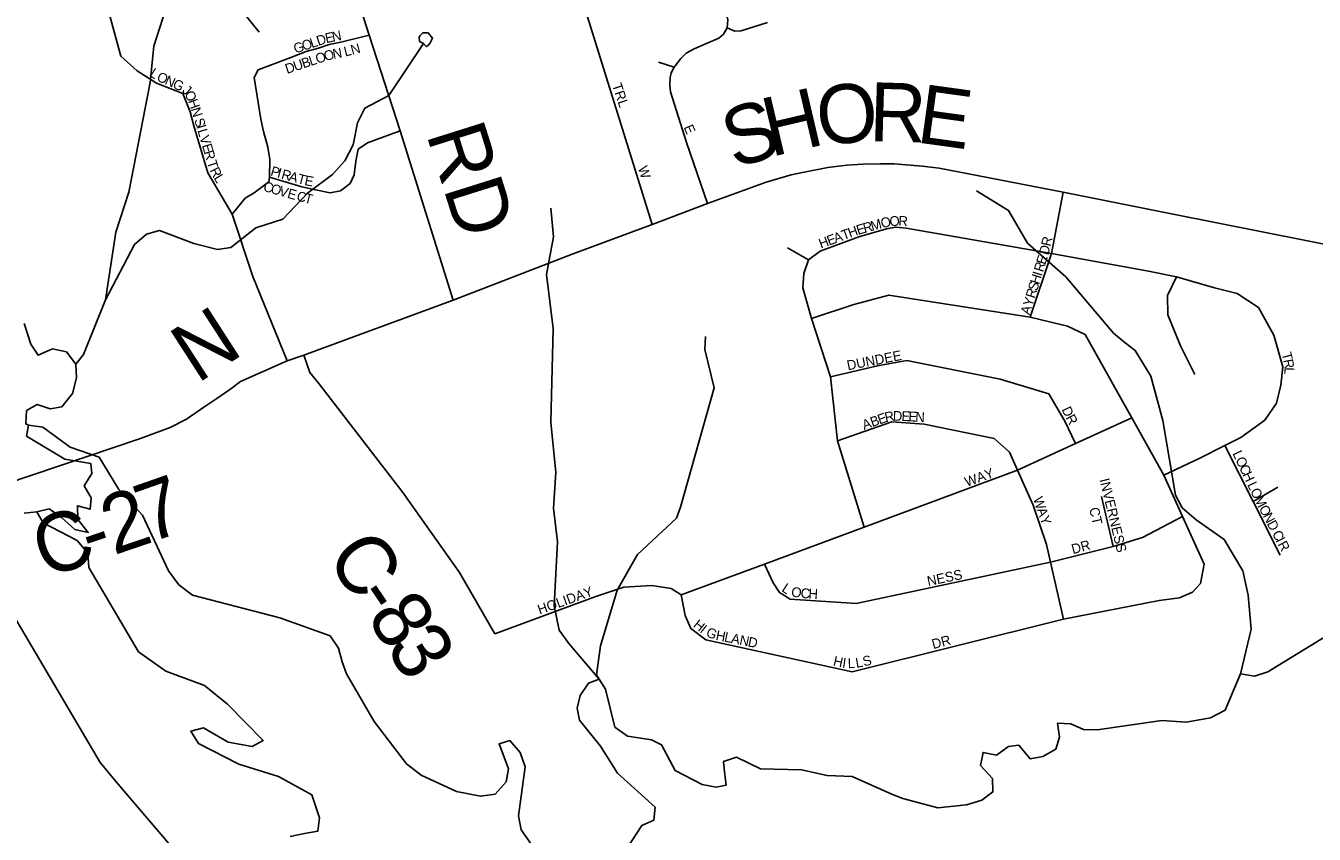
# Model space of a CAD drawing. Extents: x 1525783 to 1900577, y 218250 to 627376.
# Drawn here: x 1688647 to 1695217, y 435775 to 439896 of the extents above; entities that cross this region are included whole.
import ezdxf

# ---------------------------------------------------------------- set-up
doc = ezdxf.new("R2010")
doc.units = 0
for name, color, linetype in [('GM_X_County_Road', 7, 'Continuous'), ('GM_X_County_Road_Text', 7, 'Continuous'), ('GM_X_Major_Lake', 7, 'Continuous'), ('GM_X_Minor_Lake', 7, 'Continuous'), ('GM_X_Minor_River', 7, 'Continuous'), ('GM_X_Township_Subdivision', 7, 'Continuous'), ('GM_X_Township_Subdivision_Text', 7, 'Continuous')]:
    doc.layers.add(name, color=color, linetype=linetype)

msp = doc.modelspace()

# ---------------------------------------------------------------- linework, layer by layer
at = {"layer": 'GM_X_County_Road'}
for points in [[(1690827.2, 438497.9), (1690557, 439360.3), (1690398, 439848), (1690158, 440598.1), (1689926.7, 441314.4), (1689520.4, 442560), (1689115.8, 443745.4), (1689169.3, 444557.8), (1689169.8, 444609.9)], [(1690065.6, 438217.8), (1690827.2, 438497.9), (1691434.1, 438731.3), (1691842, 438883.6), (1692122.7, 438990.2), (1692422, 439099.7), (1692550.4, 439135.8), (1692617.2, 439150.5), (1692737.5, 439173.3), (1692833.7, 439185.3), (1692915.2, 439190.7), (1693002.1, 439192), (1693075.6, 439192), (1693217.3, 439181.3), (1693304.2, 439170.6), (1693499.3, 439133.2), (1693936.3, 439049), (1694498.6, 438936.3), (1695843.2, 438668.9)], [(1684258.4, 435873.5), (1685061.4, 436166), (1686588.5, 436826.7), (1686722.3, 436878.2), (1686872.7, 436936), (1687511.7, 437185.9), (1687952.9, 437335.6), (1688247.6, 437451.6), (1688404.4, 437513.3), (1689227.7, 437790.2), (1689382.5, 437849.2), (1689466, 437891), (1689559.4, 437954.9), (1689620.8, 437996.6), (1689692.1, 438045.8), (1689741.2, 438082.6), (1689979.6, 438188.3), (1690065.6, 438217.8)], [(1691038.4, 436797), (1690859.5, 437110.1), (1690569.3, 437517.5), (1690141.7, 438072.8), (1690095, 438129.3), (1690065.6, 438217.8)]]:
    msp.add_lwpolyline(points, dxfattribs=at)
at = {"layer": 'GM_X_Major_Lake'}
for points in [[(1691270.8, 435660.6), (1691173.1, 435796.8), (1691160.4, 435869.2), (1691193.2, 436119.2), (1691168.5, 436191.9), (1691115.5, 436253), (1691061, 436235.9), (1691108.8, 436108.7), (1691097.5, 436042.7), (1691040.2, 435979.6), (1690965.8, 435968.9), (1690843.9, 435993.1), (1690663, 436076.5), (1690587.9, 436134), (1690423.5, 436349.5), (1690281.7, 436592.7), (1690260.8, 436653.2), (1690242, 436723.7), (1690199.1, 436786.6), (1689942.1, 436877.5), (1689497.2, 436993.7), (1689428, 437047), (1689375.2, 437118.2), (1689242.1, 437401.3), (1689122.3, 437531.8), (1689021.1, 437698), (1688873.7, 437748.8), (1688733.2, 437849.5), (1688661.3, 437860.9), (1688650.2, 437804.9), (1688846.5, 437687.1), (1688978.4, 437664.7), (1688983.5, 437614.5), (1688944.2, 437551), (1688981.1, 437490.2), (1688976, 437432.1), (1688910.2, 437449.3), (1688912.9, 437379.1), (1688965.8, 437314), (1688897.9, 437329.2), (1688828.9, 437390.6), (1688765.6, 437433.9), (1688703.1, 437418.9), (1688736.1, 437362.2), (1688908.9, 437272.9), (1688963.8, 437207.7), (1688968.5, 437135.5), (1689221.1, 436705.8), (1689361.6, 436607.1), (1689558.8, 436533.4), (1689675.3, 436439), (1689858.3, 436253.3), (1689801.6, 436222.2), (1689679.7, 436244.5), (1689552.7, 436316.9), (1689488.2, 436300), (1689527.2, 436237.2), (1689733.7, 436133.2), (1689935.1, 436069.5), (1690105.8, 435976.2), (1690145.7, 435859.2), (1690136.4, 435791.1), (1690068, 435778.3), (1689995.5, 435763.6)], [(1695471.2, 436903.9), (1694980.3, 436603.7), (1694913.6, 436580.8), (1694841.7, 436592.1), (1694764, 436407), (1694689, 436368.2), (1694564.3, 436346.3), (1694440.1, 436354.5), (1694110.4, 436308.2), (1694040.2, 436309.4), (1693976.6, 436338.6), (1693908.5, 436341.8), (1693919.1, 436269.4), (1693900, 436209.6), (1693833.1, 436170.7), (1693768.7, 436159.8), (1693711.8, 436229), (1693657.5, 436221.9), (1693596.6, 436178.9), (1693528.6, 436192.1), (1693515.4, 436126.2), (1693576.3, 436058.9), (1693579, 435990.7), (1693522.1, 435949.6), (1693443.4, 435924.9), (1693298.8, 435909.4), (1693119.2, 435956.7), (1693067.4, 435977.7), (1692860.6, 436069.6), (1692734.3, 436073.8), (1692602.6, 436104.2), (1692394.1, 436107.9), (1692270.9, 436168.3), (1692204.3, 436145.4), (1692209.3, 436093.2), (1692218.1, 436024.8), (1692167.8, 436015.7)], [(1692167.8, 436015.7), (1692095.8, 436029), (1691958.8, 436099.6), (1691889.1, 436231.2), (1691837.4, 436256.2), (1691715.4, 436274.4), (1691650.2, 436321.7), (1691603.6, 436515), (1691570.5, 436565.7), (1691516, 436544.6), (1691474.7, 436483.2), (1691459.4, 436417.3), (1691470.3, 436356.9), (1691578.1, 436224.7), (1691663.8, 436086.8), (1691857.1, 435912.9), (1691849.8, 435846.9), (1691789.1, 435819.9), (1691712.8, 435702.9)]]:
    msp.add_lwpolyline(points, dxfattribs=at)
at = {"layer": 'GM_X_Minor_Lake'}
for points in [[(1690674.6, 439806.2), (1690688.3, 439790), (1690700.5, 439797.8), (1690708.8, 439809.6), (1690721.2, 439833.5), (1690699.7, 439859.9), (1690671.6, 439860.5), (1690657.3, 439844.7), (1690653.1, 439836.7), (1690654.7, 439816.6)], [(1690654.7, 439816.6), (1690674.6, 439806.2)]]:
    msp.add_lwpolyline(points, dxfattribs=at)
at = {"layer": 'GM_X_Minor_River'}
for points in [[(1689054.1, 438499.6), (1689106.7, 438843.5), (1689172.7, 439048.9), (1689281.4, 439606.5), (1689300.9, 439792.7), (1689360.6, 439982.1)], [(1688901.6, 438171.4), (1688940.7, 438220.8), (1689054.1, 438499.6), (1689201.8, 438781.7), (1689262.9, 438834.7), (1689329.4, 438853.6), (1689504.6, 438786.3), (1689624.4, 438756.1), (1689692.7, 438766.9), (1689820.9, 438866.9), (1689958.1, 438910.6), (1690082.9, 439042.7), (1690211, 439138.7), (1690274.4, 439207.7), (1690316, 439289.2), (1690338.2, 439401.1), (1690375.7, 439476.7), (1690499.2, 439540.6), (1690674.6, 439806.2)], [(1694841.7, 436592.1), (1694896.1, 436819.8), (1694881.3, 436994.5), (1694853.5, 437117.3), (1694758.2, 437277.4), (1694615.7, 437378.2), (1694544.7, 437439.6), (1694509.8, 437504.4), (1694444.7, 437884.5), (1694384.7, 438110.2), (1694305, 438241.9), (1694253.6, 438280.9), (1694194.3, 438330.1), (1693951, 438617.1), (1693755.7, 438789), (1693658.5, 438955.2), (1693495.9, 439054.3)], [(1691570.5, 436565.7), (1691415.5, 436746.9), (1691366.6, 436816), (1691340.9, 436938.8), (1691359, 437265.3), (1691338.2, 437438.1), (1691349.6, 437618.4), (1691324.3, 437875.5), (1691337.2, 438352.6), (1691302.2, 438627.9), (1691337.9, 438819.8), (1691324.6, 438966.4)], [(1688661.3, 437860.9), (1688647.3, 437867.1), (1688650.6, 437935.2), (1688705.3, 437966.3), (1688771.1, 437943.1), (1688831.4, 437954.1), (1688884.8, 438021.3), (1688906.3, 438101.1), (1688901.6, 438171.4), (1688854.7, 438234.4), (1688782.8, 438249.7), (1688710, 438216.9), (1688673, 438273.8), (1688638.8, 438378.6)], [(1691570.5, 436565.7), (1691556.9, 436588), (1691577.7, 436736), (1691663.2, 437019.3), (1691766.9, 437201.9), (1691964.8, 437386.9), (1691985.9, 437442.7), (1692157.7, 438051.2), (1692109.2, 438246.6), (1692112.5, 438312.7)], [(1688703.1, 437418.9), (1688638.8, 437412.1)]]:
    msp.add_lwpolyline(points, dxfattribs=at)
at = {"layer": 'GM_X_Township_Subdivision'}
for points in [[(1692122.7, 438990.2), (1692015.7, 439300.6), (1691934.2, 439560.3), (1691930.7, 439595.2), (1691933.1, 439632.5), (1691938.9, 439655.8), (1691952.8, 439684.9), (1691987.8, 439730.4), (1692014.6, 439756), (1692055.3, 439778.1), (1692181.1, 439834), (1692205.6, 439853.8), (1692223.1, 439885.3), (1692226.6, 439927.2), (1692220.7, 439957.5), (1692074, 440371), (1692053, 440405.9), (1692029.7, 440418.7)], [(1689979.6, 438188.3), (1689805.1, 438618.3), (1689699.5, 438935.2), (1689576.1, 439147.1), (1689504.1, 439386.7), (1689484.7, 439457.1), (1689447.4, 439551.8), (1689313.5, 439603.2), (1689215.8, 439666.3), (1689132.3, 439741.4), (1689076, 439946.7), (1689298.3, 440127.4), (1689449.6, 440220.6), (1689569.2, 440197.9), (1689837, 439863.8)], [(1691842, 438883.6), (1691455.5, 440124), (1691449.7, 440161.3), (1691455.5, 440203.2)], [(1692295.5, 439870.9), (1692429, 439913.2)], [(1690398, 439848), (1690252.9, 439812.5), (1690194, 439801.2), (1690139, 439782.2), (1690076.3, 439765.1), (1689998.5, 439734.7), (1689880.7, 439691), (1689831.3, 439672), (1689811.4, 439632.1), (1689845.4, 439419.7), (1689858.9, 439357.4), (1689880.7, 439277.2), (1689892.2, 439214.5), (1689890, 439125.3), (1689886.6, 439100.1), (1689811.9, 439044.6), (1689765.5, 439016.9), (1689699.5, 438935.2)], [(1692223.1, 439885.3), (1692262.5, 439869.6), (1692295.5, 439870.9)], [(1691952.8, 439684.9), (1691873.7, 439710.6)], [(1690557, 439360.3), (1690390, 439300.3), (1690341.5, 439266.7), (1690330.9, 439206.5), (1690322.3, 439136.3), (1690301.8, 439092.4), (1690251.3, 439054.7), (1690199, 439045.1), (1690125, 439059.8), (1690055.5, 439075), (1689890, 439125.3)], [(1693873.8, 438725), (1693877.5, 438736.2), (1693936.3, 439049)], [(1692921.5, 437340.2), (1692786.8, 437780.9), (1692750.8, 438106.7), (1692654.6, 438403.4), (1692609.1, 438561.1), (1692614.5, 438633.3), (1692638.6, 438702.8), (1692697.4, 438748.2), (1692895.2, 438820.4), (1693036.8, 438860.5), (1693083.6, 438869.9), (1693137.1, 438864.5), (1693877.5, 438736.2), (1694372, 438645.3), (1694515, 438617.3), (1694708.8, 438560.4), (1694824.4, 438531.6), (1694932.9, 438460.9), (1695011.7, 438318.7), (1695058, 438157.1), (1695047.8, 438065.1), (1695025.5, 437973.3), (1694965.4, 437886.5), (1694843, 437797), (1694762.1, 437756.1), (1694634.1, 437691.5), (1694449.7, 437605.6)], [(1692531.6, 438763.8), (1692638.6, 438702.8)], [(1693769.5, 438411.8), (1693873.8, 438725)], [(1694608.2, 438119.4), (1694535.5, 438265.6), (1694471.2, 438423.5), (1694469.5, 438521.9), (1694515, 438617.3)], [(1691988.5, 436994.8), (1692010.3, 436890.4), (1692038.8, 436823.6), (1692115.5, 436765.6), (1692861, 436603.7), (1693939.4, 436871.3), (1694426.5, 436966.2), (1694531, 436979.8), (1694595.9, 437008.4), (1694637, 437053.6), (1694655.3, 437151.5), (1694545.1, 437394.9), (1694449.7, 437605.6), (1694287, 437897.5), (1694050, 438323), (1693958.8, 438365.3), (1693769.5, 438411.8), (1693048.8, 438522.9), (1692869.4, 438475), (1692654.6, 438403.4)], [(1692750.8, 438106.7), (1692990.2, 438163.3), (1693139.1, 438189.9), (1693615.7, 438094.5), (1693864.5, 438020.4), (1693945.3, 437880.1), (1694000.8, 437766.4)], [(1691038.4, 436797), (1691553.8, 436987.4), (1691697.2, 437034.2), (1691839.6, 437042.9), (1691937.4, 437028.6), (1691988.5, 436994.8), (1692413.5, 437152.1), (1692921.5, 437340.2), (1693704.4, 437630.7), (1694000.8, 437766.4), (1694287, 437897.5)], [(1693939.4, 436871.3), (1693872.7, 437162.9), (1693852.2, 437252.5), (1693784.8, 437452.6), (1693704.4, 437630.7), (1693663, 437722.3), (1693584.5, 437792.3), (1693227.6, 437864.8), (1693063.6, 437876.7), (1692786.8, 437780.9)], [(1695043.2, 437198.6), (1694905.3, 437472.1), (1694762.1, 437756.1)], [(1695031.4, 437543.9), (1694905.3, 437472.1)], [(1694191.6, 437241.5), (1694132.5, 437496.7)], [(1690369.5, 434926.2), (1690268.3, 434997.9), (1689993, 435160.9), (1689845.5, 435256.5), (1689701.9, 435348.1), (1689108.6, 436041.7), (1689027.2, 436140.7), (1688367.5, 437256.4), (1688247.6, 437451.6)], [(1692413.5, 437152.1), (1692459, 437056.4), (1692489.9, 437007.6), (1692545.2, 436974.2), (1692881.3, 436952.2), (1693872.7, 437162.9), (1694191.6, 437241.5), (1694342, 437287.2), (1694545.1, 437394.9)]]:
    msp.add_lwpolyline(points, dxfattribs=at)

# ---------------------------------------------------------------- texts
at = {"layer": 'GM_X_County_Road_Text'}
for s, rotation, p in [('H', 13.18629, (1692446, 439227.2)), ('O', 5.16508, (1692692.1, 439285.6)), ('R', 358.31761, (1692945.5, 439309.1)), ('E', 352.17172, (1693183.4, 439302.6)), ('S', 18.62427, (1692261.4, 439164.6)), ('RD', 287.50079, (1690688, 439345.4)), ('N', 32.83831, (1689521.2, 438069.6)), ('7', 19.29768, (1689273.2, 437257.1)), ('2', 18.77029, (1689095.4, 437196.6)), ('C', 18.66821, (1688744.7, 437078.1)), ('-', 18.69116, (1688978.3, 437157)), ('C', 304.66653, (1690173.6, 437186.8)), ('-', 303.95854, (1690313.2, 436984.9)), ('8', 302.81247, (1690381.1, 436884.1)), ('3', 301.24579, (1690480.1, 436730.6))]:
    msp.add_text(s, height=300, rotation=rotation, dxfattribs=at).set_placement(p)
at = {"layer": 'GM_X_Township_Subdivision_Text'}
for s, rotation, p in [('O', 18.57317, (1690064.1, 439768.4)), ('L', 18.57317, (1690105.8, 439782.4)), ('D', 18.57317, (1690139.1, 439793.6)), ('E', 12.64439, (1690179.5, 439807.3)), ('N', 11.44283, (1690213.6, 439814.9)), ('G', 18.57317, (1690022.3, 439754.4)), ('O', 17.88205, (1690133.6, 439702.2)), ('O', 16.28468, (1690175.1, 439715.6)), ('N', 9.951, (1690216, 439727.6)), ('L', 14.31375, (1690276.2, 439739.2)), ('N', 15.40082, (1690311.3, 439748.1)), ('D', 18.43495, (1689979.3, 439650.8)), ('U', 18.44132, (1690021, 439664.7)), ('B', 18.43788, (1690062.8, 439678.6)), ('L', 18.40039, (1690100.3, 439691.2)), ('L', 325.78701, (1689274.2, 439643.1)), ('O', 334.75038, (1689310.7, 439619.1)), ('N', 336.32913, (1689351.9, 439599.7)), ('G', 335.76229, (1689392.1, 439582.1)), ('J', 320.66447, (1689441.3, 439560.4)), ('O', 295.78291, (1689454.8, 439550.9)), ('TRL', 288.43223, (1691636, 439594.5)), ('H', 289.84494, (1689473.4, 439512.6)), ('N', 287.88206, (1689488.1, 439471.6)), ('S', 286.79344, (1689505.4, 439417.3)), ('I', 286.76205, (1689515.6, 439383.6)), ('L', 286.76729, (1689521.9, 439362.6)), ('E', 293.18729, (1692000.9, 439379.6)), ('V', 286.78223, (1689532.1, 439328.9)), ('E', 286.76729, (1689544.8, 439286.7)), ('R', 286.77776, (1689554.9, 439253)), ('T', 286.89117, (1689570.2, 439202.4)), ('R', 296.58691, (1689583.9, 439160.1)), ('P', 343.8895, (1689891.7, 439134.1)), ('I', 343.91223, (1689925.5, 439124.4)), ('R', 343.90784, (1689946.7, 439118.3)), ('W', 288.44042, (1691768, 439172.1)), ('L', 301.25118, (1689603.7, 439120.8)), ('C', 343.67762, (1689854.3, 439056)), ('A', 343.89545, (1689984.7, 439107.3)), ('T', 345.30528, (1690028.3, 439094.7)), ('E', 348.9314, (1690065.7, 439085)), ('O', 343.70346, (1689892.4, 439044.8)), ('V', 343.73898, (1689934.6, 439032.5)), ('E', 344.13323, (1689977.2, 439020.1)), ('C', 344.79719, (1690024.4, 439006.7)), ('T', 345.70107, (1690063.4, 438996.1)), ('M', 15.46757, (1692962.5, 438850.3)), ('O', 13.20923, (1693012.9, 438864.3)), ('O', 4.85803, (1693053.8, 438874)), ('R', 356.45245, (1693095.7, 438877.7)), ('E', 20.37058, (1692743, 438775.2)), ('A', 20.38768, (1692776, 438787.5)), ('T', 20.38556, (1692817.3, 438802.8)), ('H', 19.7347, (1692850.1, 438815)), ('E', 16.70709, (1692890.9, 438829.6)), ('R', 15.58519, (1692924.3, 438839.7)), ('H', 20.38463, (1692701.8, 438759.9)), ('D', 75.4538, (1693861.2, 438724.4)), ('R', 77.39233, (1693872.6, 438768.8)), ('E', 72.51556, (1693845.9, 438675.6)), ('I', 72.55194, (1693827.4, 438616.8)), ('R', 72.53294, (1693834, 438637.8)), ('S', 72.51556, (1693803.6, 438541.2)), ('H', 72.54031, (1693814.2, 438574.8)), ('Y', 72.54031, (1693778.5, 438461.5)), ('R', 72.54023, (1693791.7, 438503.5)), ('A', 72.53256, (1693765.3, 438419.5)), ('DUNDEE', 10.92041, (1692839.4, 438139.9)), ('T', 284.46689, (1695050.5, 438225.6)), ('R', 280.57639, (1695059.1, 438192.4)), ('L', 267.84148, (1695066.2, 438156.4)), ('E', 19.32486, (1693000.8, 437863.6)), ('R', 12.43398, (1693032.5, 437874.8)), ('D', 358.97268, (1693068.1, 437883)), ('E', 357.04753, (1693111.6, 437882.3)), ('E', 357.02024, (1693146.8, 437880.5)), ('N', 357.15563, (1693182, 437878.6)), ('D', 295.19648, (1693928, 437941)), ('R', 297.96125, (1693947.9, 437898.8)), ('A', 19.31274, (1692921.9, 437835.9)), ('B', 19.34651, (1692963.4, 437850.5)), ('L', 295.31889, (1694799.2, 437716.7)), ('O', 295.31396, (1694814.2, 437684.9)), ('C', 295.31615, (1694833, 437645.1)), ('WAY', 19.5318, (1693445.5, 437545.6)), ('INVERNESS', 283.67222, (1694122.2, 437582.9)), ('H', 295.31396, (1694850, 437609.3)), ('L', 295.33058, (1694874.4, 437557.5)), ('O', 295.41681, (1694889.5, 437525.7)), ('W', 287.83948, (1693783.4, 437486.1)), ('M', 297.02878, (1694909.1, 437484.5)), ('A', 289.64558, (1693801.5, 437430)), ('Y', 289.81696, (1693816.3, 437388.4)), ('CT', 283.24411, (1694069.3, 437435.5)), ('O', 297.69367, (1694933.4, 437436.9)), ('N', 297.67917, (1694953.8, 437398)), ('D', 297.67833, (1694974.3, 437359)), ('DR', 15.52599, (1693987.3, 437202.5)), ('C', 297.69147, (1695000.9, 437308.3)), ('I', 297.67917, (1695019.3, 437273.3)), ('R', 297.67556, (1695029.5, 437253.8)), ('NESS', 11.82024, (1693248.7, 437039.9)), ('HOLIDAY', 19.59278, (1691267.5, 436894.4)), ('L', 326.41602, (1692498, 437016.6)), ('O', 348.99994, (1692547.1, 436989)), ('C', 356.48701, (1692597.4, 436979.7)), ('H', 356.43457, (1692636.9, 436977.3)), ('H', 320.99202, (1692046.7, 436835.5)), ('I', 320.97826, (1692080.9, 436807.8)), ('G', 337.93268, (1692111.9, 436785.8)), ('H', 349.06661, (1692162.8, 436766.2)), ('L', 348.50253, (1692205.9, 436757.9)), ('A', 348.49291, (1692240.4, 436750.9)), ('N', 348.51875, (1692283.5, 436742.1)), ('D', 348.49291, (1692326.6, 436733.4)), ('DR', 14.7379, (1693274.7, 436718.6)), ('H', 347.12585, (1692761.3, 436635.9)), ('I', 351.70867, (1692808.5, 436625.3)), ('L', 0.87433, (1692839, 436621.6)), ('L', 10.03998, (1692882.9, 436622.9)), ('S', 14.62281, (1692921.8, 436630))]:
    msp.add_text(s, height=50, rotation=rotation, dxfattribs=at).set_placement(p)

doc.saveas('drawing.dxf')
